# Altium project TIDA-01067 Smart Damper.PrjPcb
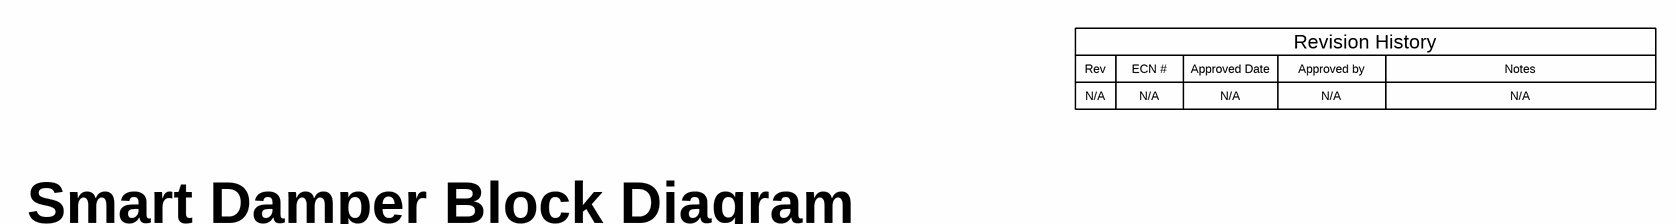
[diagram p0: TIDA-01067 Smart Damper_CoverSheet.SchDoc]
CopyrightYear: 2016; Orderable: N/A; PCB_Layout: Krypton Solutions/RS; PCB_Rev: A; PRJ_Customer: Public Release; PRJ_Engineer: Jarrod Krebs; PRJ_Number: TIDA-01067; PRJ_Title: TIDA-01067 Smart Damper; SCH_Rev: A; TechSupport: http://www.ti.com/support; TID: 01067
4 sheets, 103 parts. Net scope: global (net labels, ports and power ports of the same name join across sheets).
Board file: TIDA-01067 Smart Damper.PcbDoc
Sheets:
  TIDA-01067 Smart Damper_CoverSheet.SchDoc
  TIDA-01067 Smart Damper_Hardware.SchDoc
  TIDA-01067 Smart Damper_Sheet1.SchDoc
  TIDA-01067 Smart Damper_Sheet2.SchDoc

## Sheet TIDA-01067 Smart Damper_CoverSheet.SchDoc: Cover
size 431 x 279 mm; Date: Not shown in title block; ApprovedBy: Not shown in title block; CheckedBy: Not shown in title block; Author: Not shown in title block; CompanyName: Not shown in title block; Engineer: Not shown in title block; Organization: Not shown in title block; Address1: Not shown in title block; Address2: Not shown in title block; Address3: Not shown in title block; Address4: Not shown in title block; DocumentNumber: 1; Revision: Use project parameter SCH_Rev; SheetNumber: 1; SheetTotal: 4; PageSetup: Record=PageOptions¦CenterHorizontal=True¦CenterVertical=True¦PrintScale=1.00¦XCorrection=1.00¦YCorrection=1.00¦PrintKind=0¦BorderSize=5000000¦LeftOffset=0¦BottomOffset=0¦Orientation=2¦PaperLength=1000¦PaperWidth=1000¦Scale=100¦PaperSource=15¦PrintQuality=-3¦MediaType=1¦DitherType=10¦PrintScaleMode=1¦PaperKind=Letter¦PaperIndex=1

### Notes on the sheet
- Rev
- N/A
- ECN #
- Approved Date
- Approved by
- Revision History
- Notes
- Smart Damper Block Diagram

## Sheet TIDA-01067 Smart Damper_Hardware.SchDoc: Hardware
size 431 x 279 mm; Date: Not shown in title block; ApprovedBy: Not shown in title block; CheckedBy: Not shown in title block; Author: Not shown in title block; CompanyName: Not shown in title block; Engineer: Not shown in title block; Organization: Not shown in title block; Address1: Not shown in title block; Address2: Not shown in title block; Address3: Not shown in title block; Address4: Not shown in title block; DocumentNumber: 4; Revision: Use project parameter SCH_Rev; SheetNumber: 4; SheetTotal: 4; PageSetup: Record=PageOptions¦CenterHorizontal=True¦CenterVertical=True¦PrintScale=1.00¦XCorrection=1.00¦YCorrection=1.00¦PrintKind=0¦BorderSize=5000000¦LeftOffset=0¦BottomOffset=0¦Orientation=2¦PaperLength=1000¦PaperWidth=1000¦Scale=100¦PaperSource=15¦PrintQuality=600¦MediaType=1¦DitherType=10¦PaperKind=Letter¦PrintScaleMode=1
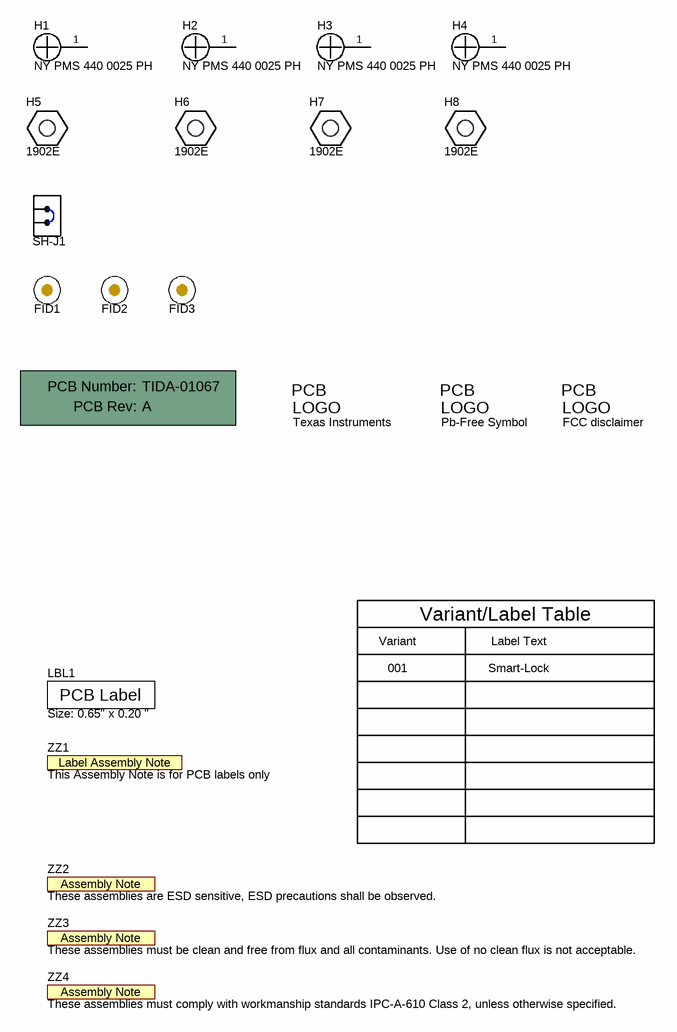
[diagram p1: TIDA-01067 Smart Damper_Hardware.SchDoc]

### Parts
!PCB1  Printed Circuit Board  (value not drawn)  (mechanical)
FID1  Fiducial  [Fiducial10-20]  (value not drawn)
FID2  Fiducial  [Fiducial10-20]  (value not drawn)
FID3  Fiducial  [Fiducial10-20]  (value not drawn)
H1  NY PMS 440 0025 PH  [NY PMS 440 0025 PH]
H2  NY PMS 440 0025 PH  [NY PMS 440 0025 PH]
H3  NY PMS 440 0025 PH  [NY PMS 440 0025 PH]
H4  NY PMS 440 0025 PH  [NY PMS 440 0025 PH]
H5  1902E  [Keystone_1902E]
H6  1902E  [Keystone_1902E]
H7  1902E  [Keystone_1902E]
H8  1902E  [Keystone_1902E]
LBL1  Size: 0.65" x 0.20 "  [Label_650x200]
Logo1  Texas Instruments  [TI_Stacked_Overlay_Small]  (no BOM)
Logo2  Pb-Free Symbol  [Pb-Free_Overlay_Small]  (no BOM)
Logo3  FCC disclaimer  [FCC_disclaimer]  (no BOM)
SH-J1  969102-0000-DA  [SNT-100-BK-G]  (value not drawn)
ZZ1  This Assembly Note is for PCB labels only  [AssemblyNoteLabel]  (no BOM)
ZZ2  These assemblies are ESD sensitive, ESD precautions shall be observed.  [AssemblyNote]  (no BOM)
ZZ3  These assemblies must be clean and free from flux and all contaminants. Use of no clean flux is not acceptable.  [AssemblyNote]  (no BOM)
ZZ4  These assemblies must comply with workmanship standards IPC-A-610 Class 2, unless otherwise specified.  [AssemblyNote]  (no BOM)

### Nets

Not connected (* = marked no-connect by the designer): H1 1; H2 1; H3 1; H4 1

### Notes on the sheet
- Variant
- Variant/Label Table
- Label Text
- 001
- Smart-Lock

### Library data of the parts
!PCB1 = PCB: Manufacturer: Any; PartNumber: TIDA-01067; SymbolCreator: a0412235
FID1-FID3 = Fiducial: Fiducial mark.  There is nothing to buy or mount.; SymbolCreator: codlsc
H1-H4 = NY PMS 440 0025 PH: Machine Screw, Round, #4-40 x 1/4, Nylon, Philips panhead; Manufacturer: B&F Fastener Supply; CompType: Hardware; SymbolCreator: codlsc; U/M: EA
H5-H8 = 1902E: Standoff, Hex, 1"L #4-40 Nylon; Manufacturer: Keystone; CompType: Hardware; SymbolCreator: a0412235
LBL1 = THT-14-423-10: Thermal Transfer Printable Labels, 0.650" W x 0.200" H - 10,000 per roll; Manufacturer: Brady; SymbolCreator: a0412235; CompType: Label
Logo1 = TI_Logo: Texas Instrument Corporate Signature; SymbolCreator: codlsc
Logo2 = Pb-Free: SymbolCreator: a0412235
Logo3 = FCC_disclaimer: SymbolCreator: codlsc
SH-J1 = 969102-0000-DA: Shunt, 100mil, Gold plated, Black; Manufacturer: 3M; Alternate Manufacturer: Samtec; Value: 1x2; Note: You can "mate" this to a header by matching the designator.  i.e. use SH-J3 for header J3
ZZ1 = AssemblyNoteLabel: SymbolCreator: a0412235
ZZ2-ZZ4 = AssemblyNote: SymbolCreator: codlsc

## Sheet TIDA-01067 Smart Damper_Sheet1.SchDoc: Schematic
size 431 x 279 mm; Date: Not shown in title block; ApprovedBy: Not shown in title block; CheckedBy: Not shown in title block; Author: Not shown in title block; CompanyName: Not shown in title block; DrawnBy: Aramis P. Alvarez; Engineer: Not shown in title block; Organization: Not shown in title block; Address1: Not shown in title block; Address2: Not shown in title block; Address3: Not shown in title block; Address4: Not shown in title block; DocumentNumber: 2; Revision: Use project parameter SCH_Rev; SheetNumber: 2; SheetTotal: 4; PageSetup: Record=PageOptions¦CenterHorizontal=True¦CenterVertical=True¦PrintScale=1.00¦XCorrection=1.00¦YCorrection=1.00¦PrintKind=0¦BorderSize=5000000¦LeftOffset=0¦BottomOffset=0¦Orientation=2¦PaperLength=1000¦PaperWidth=1000¦Scale=100¦PaperSource=15¦PrintQuality=600¦MediaType=1¦DitherType=10¦PaperKind=Letter¦PrintScaleMode=1
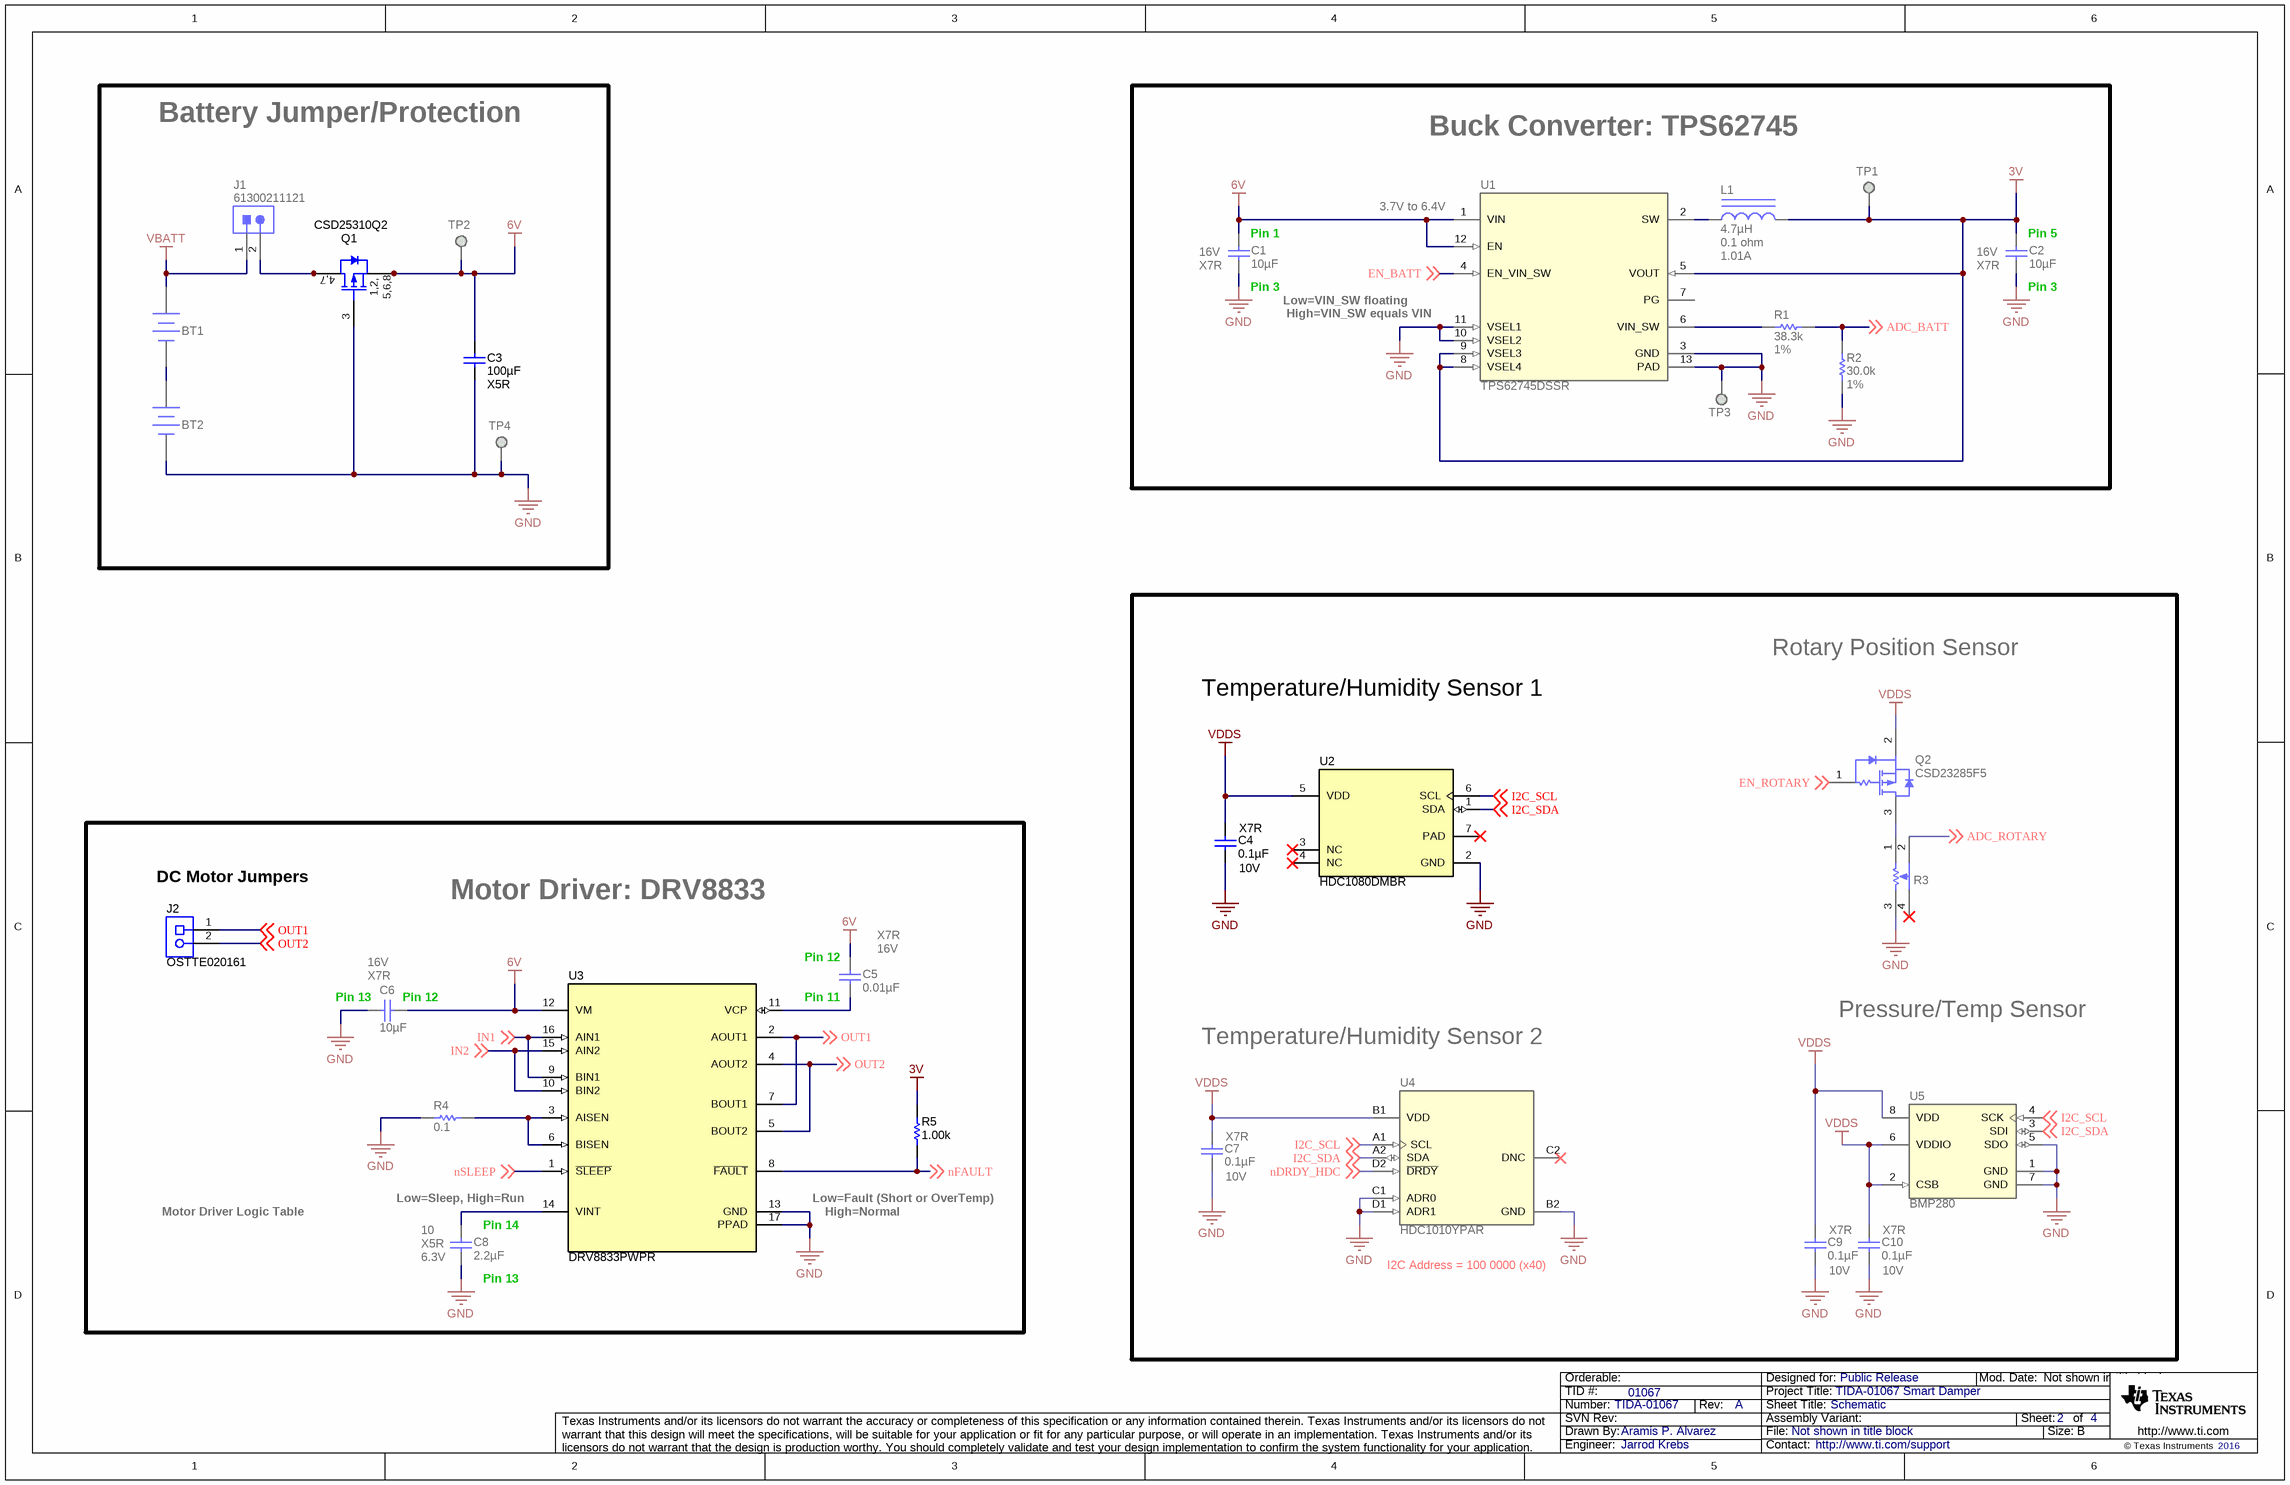
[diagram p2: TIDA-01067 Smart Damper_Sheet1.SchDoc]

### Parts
BT1  2462  [Keystone_2462]  (value not drawn)
BT2  2462  [Keystone_2462]  (value not drawn)
C1  ValueDisplayed: 10µF  Value2: 16V  TempCo: X7R  [0805_HV]  (hidden comment: EMK212BB7106MG-T)
C2  ValueDisplayed: 10µF  Value2: 16V  TempCo: X7R  [0805_HV]  (hidden comment: EMK212BB7106MG-T)
C3  ValueDisplayed: 100µF  TempCo: X5R  [1206_190]  (hidden comment: C3216X5R1A107M160AC)
C4  ValueDisplayed: 0.1µF  Value2: 10V  TempCo: X7R  [0402L]  (hidden comment: GRM155R71A104KA01D)
C5  ValueDisplayed: 0.01µF  Value2: 16V  TempCo: X7R  [0402]  (hidden comment: C1005X7R1C103K050BA)
C6  ValueDisplayed: 10µF  Value2: 16V  TempCo: X7R  [0805_HV]  (hidden comment: EMK212BB7106MG-T)
C7  ValueDisplayed: 0.1µF  Value2: 10V  TempCo: X7R  [0402L]  (hidden comment: GRM155R71A104KA01D)
C8  ValueDisplayed: 2.2µF  Tolerance_%: 10  Value2: 6.3V  TempCo: X5R  [0603]  (hidden comment: C0603C225K9PACTU)
C9  ValueDisplayed: 0.1µF  Value2: 10V  TempCo: X7R  [0402L]  (hidden comment: GRM155R71A104KA01D)
C10  ValueDisplayed: 0.1µF  Value2: 10V  TempCo: X7R  [0402L]  (hidden comment: GRM155R71A104KA01D)
J1  61300211121  [WURTH_61300211121]
J2  OSTTE020161  [On-Shore_OSTTE020161]
L1  ValueDisplayed: 4.7µH  Value1: 0.1 ohm  Value2: 1.01A  [CBC3225]  (hidden comment: CBC3225T4R7MR)
Q1  CSD25310Q2  [TRANS_NexFET_Q2]
Q2  CSD23285F5  [YJK0003A]
R1  ValueDisplayed: 38.3k  Value1: 1%  [0603]  (hidden comment: RC0603FR-0738K3L)
R2  ValueDisplayed: 30.0k  Value1: 1%  [0603]  (hidden comment: ERJ-3EKF3002V)
R3  EVW-AE4001B14  [Panasonic_EVW-AE4001B14]  (value not drawn)
R4  ValueDisplayed: 0.1  [1206]  (hidden comment: CSR1206FKR100)
R5  ValueDisplayed: 1.00k  [0603]  (hidden comment: ERJ-3EKF1001V)
TP1  TESTPOINT  [Keystone_5019]  (value not drawn)  (no BOM)
TP2  TESTPOINT  [Keystone_5019]  (value not drawn)  (no BOM)
TP3  TESTPOINT  [Keystone_5019]  (value not drawn)  (no BOM)
TP4  TESTPOINT  [Keystone_5019]  (value not drawn)  (no BOM)
U1  TPS62745DSSR  [DSS0012A]
U2  HDC1080DMBR  [DMB0006A]
U3  DRV8833PWPR  [PWP0016C_N]
U4  HDC1010YPAR  [YPA0008AGAE]
U5  BMP280  [LGA8-2X2_5MM_0_65]

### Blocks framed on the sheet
Battery Jumper/Protection: BT1 BT2 C3 J1 Q1 TP2 TP4
Buck Converter: TPS62745: C1 C2 L1 R1 R2 TP1 TP3 U1
I2C Address = 100 0000 (x40): C4 C7 C9 C10 Q2 R3 U2 U4 U5
Motor Driver: DRV8833: C5 C6 C8 J2 R4 R5 U3

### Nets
3V: C2.2 L1.2 R5.2 TP1.1 U1.5(VOUT) U1.8(VSEL4) U1.9(VSEL3)
6V: C1.2 C3.2 C5.2 C6.2 Q1.1(S) Q1.2(S) Q1.5(S) Q1.6(S) Q1.8(S) TP2.1 U1.1(VIN) U1.12(EN) U3.12(VM)
GND: BT2.2(-) C1.1 C2.1 C3.1 C4.1 C6.1 C7.1 C8.2 C9.1 C10.1 Q1.3(G) R2.2 R3.3 R4.1 TP3.1 TP4.1 U1.3(GND) U1.10(VSEL2) U1.11(VSEL1) U1.13(PAD) U2.2(GND) U3.13(GND) U3.17(PPAD) U4.B2(GND) U4.C1(ADR0) U4.D1(ADR1) U5.1(GND) U5.5(SDO) U5.7(GND)
VBATT: BT1.1(+) J1.1
VDDS: C4.2 C7.2 C9.2 C10.2 Q2.2(S) U2.5(VDD) U4.B1(VDD) U5.2(CSB) U5.6(VDDIO) U5.8(VDD)
ADC_BATT: R1.1 R2.1 ; off-sheet ADC_BATT
ADC_ROTARY: R3.2 ; off-sheet ADC_ROTARY
EN_BATT: U1.4(EN_VIN_SW) ; off-sheet EN_BATT
EN_ROTARY: Q2.1(G) ; off-sheet EN_ROTARY
I2C_SCL: U2.6(SCL) U4.A1(SCL) U5.4(SCK) ; off-sheet I2C_SCL
I2C_SDA: U2.1(SDA) U4.A2(SDA) U5.3(SDI) ; off-sheet I2C_SDA
IN1: U3.9(BIN1) U3.16(AIN1) ; off-sheet IN1
IN2: U3.10(BIN2) U3.15(AIN2) ; off-sheet IN2
nDRDY_HDC: U4.D2(~{DRDY}) ; off-sheet nDRDY_HDC
nFAULT: R5.1 U3.8(~{FAULT}) ; off-sheet nFAULT
nSLEEP: U3.1(~{SLEEP}) ; off-sheet nSLEEP
OUT1: J2.1 U3.2(AOUT1) U3.7(BOUT1) ; off-sheet OUT1
OUT2: J2.2 U3.4(AOUT2) U3.5(BOUT2) ; off-sheet OUT2
NetBT1_2: BT1.2(-) BT2.1(+)
NetC5_1: C5.1 U3.11(VCP)
NetC8_1: C8.1 U3.14(VINT)
NetJ1_2: J1.2 Q1.4(D) Q1.7(D)
NetL1_1: L1.1 U1.2(SW)
NetQ2_3: Q2.3(D) R3.1
NetR1_2: R1.2 U1.6(VIN_SW)
NetR4_2: R4.2 U3.3(AISEN) U3.6(BISEN)

Not connected (* = marked no-connect by the designer): R3 4*; U1 7(PG); U2 3(NC)* 4(NC)* 7(PAD)*; U4 C2(DNC)*

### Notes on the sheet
- (near C1) Pin 1
- (near U1) 3.7V to 6.4V
- (near C2) Pin 5
- (near C1) Pin 3
- Low=VIN_SW floating
- (near C2) Pin 3
- High=VIN_SW equals VIN
- Temperature/Humidity Sensor 1
- Rotary Position Sensor
- (near J2) DC Motor Jumpers
- (near C5) Pin 12
- (near C6) Pin 13
- (near C6) Pin 12
- (near C5) Pin 11
- Pressure/Temp Sensor
- Temperature/Humidity Sensor 2
- Motor Driver Logic Table
- Low=Sleep, High=Run
- (near C8) Pin 14
- High=Normal
- Low=Fault (Short or OverTemp)
- (near C8) Pin 13

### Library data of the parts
BT1 BT2 = 2462: 2x AA Battery Holder, Through-hole mount; Manufacturer: Keystone
C1 C2 C6 = EMK212BB7106MG-T: CAP, CERM, 10 µF, 16 V, +/- 20%, X7R, 0805; Manufacturer: Taiyo Yuden; Polarized: N; CompType: Capacitor; Value: 10uF; U/M: EA; Cap_F: 0.00001; Tolerance_%: 20; Value1: Unknown; VDC_V: 16; TaMin_C: -55; TaMax_C: 125; Cap_Case: 0805; AEC Category: Q200
C3 = C3216X5R1A107M160AC: CAP, CERM, 100 µF, 10 V, +/- 20%, X5R, 1206_190; Manufacturer: TDK; Polarized: N; CompType: Capacitor; Value: 100uF; U/M: EA; Cap_F: 0.0001; Tolerance_%: 20; Value1: Unknown; VDC_V: 10; Value2: 10V; TaMin_C: -55; TaMax_C: 85; Cap_Case: 1206; AEC Category: Q200
C4 C7 C9 C10 = GRM155R71A104KA01D: CAP, CERM, 0.1 µF, 10 V, +/- 10%, X7R, 0402; Manufacturer: MuRata; Polarized: N; CompType: Capacitor; Value: 0.1uF; U/M: EA; Cap_F: 0.0000001; Tolerance_%: 10; Value1: Unknown; TaMin_C: -55; TaMax_C: 125; Cap_Case: 0402; AEC Category: Q200
C5 = C1005X7R1C103K050BA: CAP, CERM, 0.01 µF, 16 V, +/- 10%, X7R, 0402; Manufacturer: TDK; Polarized: N; CompType: Capacitor; Value: 0.01uF; U/M: EA; Cap_F: 0.00000001; Tolerance_%: 10; ESR_ohm: 0.0623; Value1: 0.0623 ohm; VDC_V: 16; TaMin_C: -55; TaMax_C: 125; AEC Category: Q200
C8 = C0603C225K9PACTU: CAP, CERM, 2.2 µF, 6.3 V, +/- 10%, X5R, 0603; Manufacturer: Kemet; Polarized: N; CompType: Capacitor; Value: 2.2uF; U/M: EA; Cap_F: 0.0000022; Value1: Unknown; VDC_V: 6.3; TaMin_C: -55; TaMax_C: 85; AEC Category: Q200
J1 = 61300211121: Header, 2.54 mm, 2x1, Gold, TH; Manufacturer: Wurth Elektronik eiSos; SymbolCreator: a0412235; U/M: EA
J2 = OSTTE020161: Terminal Block, 2x1, 3.5mm, TH; Manufacturer: On-Shore Technology; SymbolCreator: a0412235
L1 = CBC3225T4R7MR: Inductor, Wirewound, 4.7 µH, 1.01 A, 0.1 ohm, SMD; Manufacturer: Taiyo Yuden; Value: 4.7uH; Ind_H: 4.7E-6; Imax_A: 1.01; Irms: 1.04A @ 40C rise; Isat: 1.25A @ 30% inductance drop; DCR_ohm: 0.1; AEC Category: Q200; AEC Qualified: N
Q1 = CSD25310Q2: MOSFET, P-CH, -20 V, -20 A, SON 2x2mm; Manufacturer: Texas Instruments; Alternate Manufacturer: None; SymbolCreator: a0411947; U/M: EA; ChType: P; Value: -20V; Value1: 0.0239 ohm; Rdson45_ohm: 0.0239; Value2: 3.6 nC; QgTyp_nC: 3.6; Vgs_V: -8; AEC Category: Q101
Q2 = CSD23285F5: MOSFET, P-CH, -12 V, -3.3 A, YJK0003A (PICOSTAR-3); Manufacturer: Texas Instruments; Alternate Manufacturer: None; SymbolCreator: a0411947; U/M: EA; ChType: P; Value: -12V; Value1: 0.035 ohm; Rdson45_ohm: 0.035; Value2: 3.2 nC; QgTyp_nC: 3.2; Vgs_V: -6; SizeAreaWB_mm2: 4.3077; SizeArea_mm2: 1.0877; SizeX_mm: 1.49; SizeY_mm: 0.73; SizeZ_mm: 0.35; AEC Category: Q101; AEC Qualified: N
R1 = RC0603FR-0738K3L: RES, 38.3 k, 1%, 0.1 W, 0603; Manufacturer: Yageo America; CompType: Resistor; Value: 38.3k; Res_ohm: 38300; Value_Code: 38k3; Tolerance_%: 1; Power_W: 0.1; Value2: 0.1W; VDC_V: 150; TempCo: 200 ppm/C; EIA_Code: E96; U/M: EA; AEC Category: Q200
R2 = ERJ-3EKF3002V: RES, 30.0 k, 1%, 0.1 W, AEC-Q200 Grade 0, 0603; Manufacturer: Panasonic; CompType: Resistor; Value: 30.0k; Res_ohm: 30000; Value_Code: 30k0; Tolerance_%: 1; Power_W: 0.1; Value2: 0.1W; VDC_V: 75; TempCo: 100 ppm/C; U/M: EA; AEC Category: Q200; AEC Qualified: Y; AEC Grade: 0
R3 = EVW-AE4001B14: 10 mm GS Sensor, SMD; Manufacturer: Panasonic; SymbolCreator: Altium; SizeAreaWB_mm2: 219.24; SizeArea_mm2: 163.24; SizeX_mm: 15.4; SizeY_mm: 10.6; SizeZ_mm: 2.2
R4 = CSR1206FKR100: RES, 0.1, 1%, 0.5 W, 1206; Manufacturer: Stackpole Electronics Inc; CompType: Resistor; Value: 0.1; Value_Code: R100; Tolerance_%: 1; Power_W: 0.5; Value2: 0.5W; TempCo: 100 ppm/C; EIA_Code: E96; U/M: EA; AEC Category: Q200
R5 = ERJ-3EKF1001V: RES, 1.00 k, 1%, 0.1 W, 0603; Manufacturer: Panasonic; CompType: Resistor; Value: 1.00k; Res_ohm: 1000; Value_Code: 1k00; Tolerance_%: 1; Power_W: 0.1; Value2: 0.1W; VDC_V: 75; TempCo: 100 ppm/C; EIA_Code: E96; U/M: EA; AEC Category: Q200
TP1-TP4 = 5019: Test Point, Miniature, SMT; Manufacturer: Keystone; CompType: Test Point Loop
U1 = TPS62745DSSR: Dual-cell Ultra Low IQ Step Down Converter for Low Power Wireless Applications, DSS0012A; Alternate PartNumber: TPS62745DSST; Manufacturer: Texas Instruments; SymbolCreator: a0411947; CompType: IC; U/M: EA
U2 = HDC1080DMBR: HDC1080 Low Power, High Accuracy Digital Humidity Sensor with Temperature Sensor, DMB0006A (WSON-6); Alternate PartNumber: HDC1080DMBT; Manufacturer: Texas Instruments; SymbolCreator: a0411947; SizeArea_mm2: 9; SizeAreaWB_mm2: 16; SizeX_mm: 3; SizeZ_mm: 0.8; CompType: IC; U/M: EA
U3 = DRV8833PWPR: Dual H-Bridge Motor Driver, PWP0016C; Manufacturer: Texas Instruments; SymbolCreator: a0411947; CompType: IC; U/M: EA
U4 = HDC1010YPAR: Low Power, High Accuracy Digital Humidity Sensor with Temperature Sensor, YPA0008AGAE (DSBGA-8); Alternate PartNumber: HDC1010YPAT; Manufacturer: Texas Instruments; SymbolCreator: Altium; SizeArea_mm2: 3.2436; SizeAreaWB_mm2: 7.8736; SizeX_mm: 1.59; SizeY_mm: 2.04; SizeZ_mm: 0.675; CompType: IC; U/M: EA
U5 = BMP280: Digital Pressure Sensor, LGA8-2X2_5MM_0_65; Manufacturer: Bosch Solar Energy; SymbolCreator: Altium

## Sheet TIDA-01067 Smart Damper_Sheet2.SchDoc: Schematic
size 431 x 279 mm; Date: Not shown in title block; ApprovedBy: Not shown in title block; CheckedBy: Not shown in title block; Author: Not shown in title block; CompanyName: Not shown in title block; Engineer: Not shown in title block; Organization: Not shown in title block; Address1: Not shown in title block; Address2: Not shown in title block; Address3: Not shown in title block; Address4: Not shown in title block; DocumentNumber: 3; Revision: Use project parameter SCH_Rev; SheetNumber: 3; SheetTotal: 4; PageSetup: Record=PageOptions¦CenterHorizontal=True¦CenterVertical=True¦PrintScale=1.00¦XCorrection=1.00¦YCorrection=1.00¦PrintKind=0¦BorderSize=5000000¦LeftOffset=0¦BottomOffset=0¦Orientation=2¦PaperLength=1000¦PaperWidth=1000¦Scale=100¦PaperSource=15¦PrintQuality=600¦MediaType=1¦DitherType=10¦PaperKind=Letter¦PrintScaleMode=1
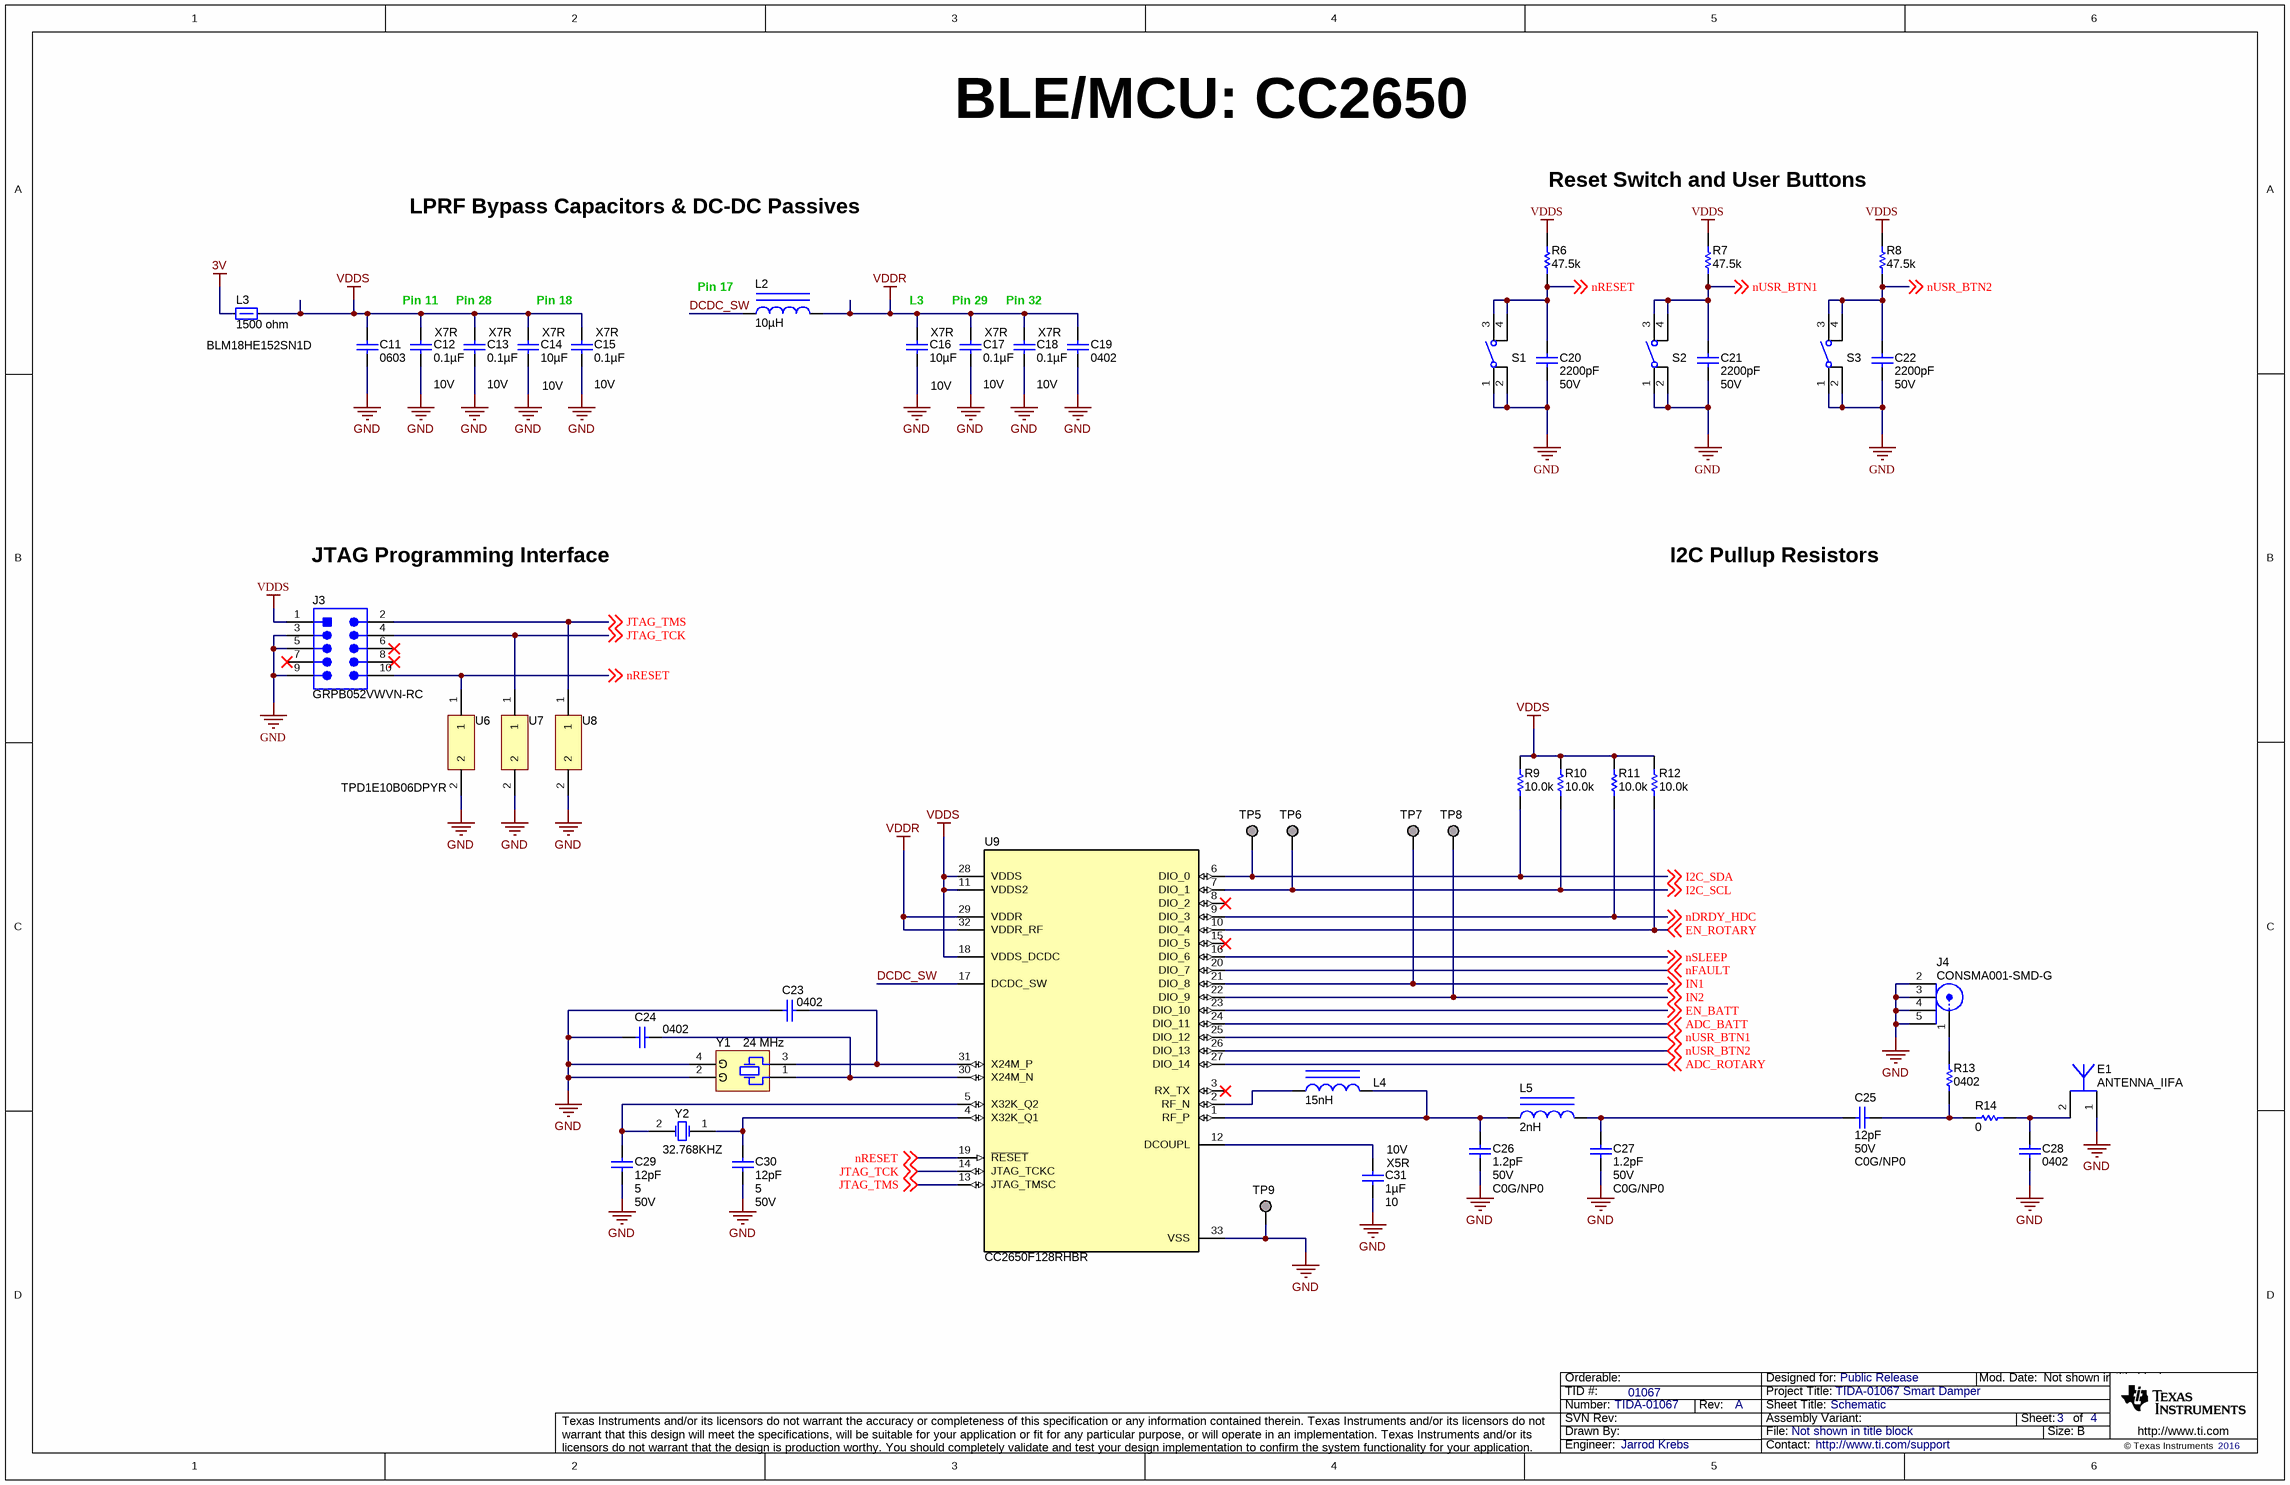
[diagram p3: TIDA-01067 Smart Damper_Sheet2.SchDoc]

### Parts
C11  C1608X5R1A106M080AC  [0603]  (value not drawn)
C12  ValueDisplayed: 0.1µF  Value2: 10V  TempCo: X7R  [0402]  (hidden comment: GRM155R71A104KA01D)
C13  ValueDisplayed: 0.1µF  Value2: 10V  TempCo: X7R  [0402]  (hidden comment: GRM155R71A104KA01D)
C14  ValueDisplayed: 10µF  Value2: 10V  TempCo: X7R  [0805_HV]  (hidden comment: GRM21BR71A106KE51L)
C15  ValueDisplayed: 0.1µF  Value2: 10V  TempCo: X7R  [0402S]  (hidden comment: GRM155R71A104KA01D)
C16  ValueDisplayed: 10µF  Value2: 10V  TempCo: X7R  [0805_HV]  (hidden comment: GRM21BR71A106KE51L)
C17  ValueDisplayed: 0.1µF  Value2: 10V  TempCo: X7R  [0402L]  (hidden comment: GRM155R71A104KA01D)
C18  ValueDisplayed: 0.1µF  Value2: 10V  TempCo: X7R  [0402L]  (hidden comment: GRM155R71A104KA01D)
C19  Cap_Case: 0402  [0402L]  (hidden comment: 885012205037)
C20  ValueDisplayed: 2200pF  Value2: 50V  [0402]  (hidden comment: C1005X7R1H222K)
C21  ValueDisplayed: 2200pF  Value2: 50V  [0402]  (hidden comment: C1005X7R1H222K)
C22  ValueDisplayed: 2200pF  Value2: 50V  [0402]  (hidden comment: C1005X7R1H222K)
C23  GRM1555C1H120JA01D  [0402]  (value not drawn)
C24  GRM1555C1H120JA01D  [0402]  (value not drawn)
C25  ValueDisplayed: 12pF  Value2: 50V  TempCo: C0G/NP0  [0402L]  (hidden comment: GRM1555C1H120JA01D)
C26  ValueDisplayed: 1.2pF  Value2: 50V  TempCo: C0G/NP0  [0402L]  (hidden comment: GRM1555C1H1R2CA01D)
C27  ValueDisplayed: 1.2pF  Value2: 50V  TempCo: C0G/NP0  [0402L]  (hidden comment: GRM1555C1H1R2CA01D)
C28  GRM1555C1H1R2CA01D  [0402]  (value not drawn)
C29  ValueDisplayed: 12pF  Tolerance_%: 5  Value2: 50V  [0402]  (hidden comment: GRM1555C1H120JA01D)
C30  ValueDisplayed: 12pF  Tolerance_%: 5  Value2: 50V  [0402]  (hidden comment: GRM1555C1H120JA01D)
C31  ValueDisplayed: 1µF  Tolerance_%: 10  Value2: 10V  TempCo: X5R  [0402]  (hidden comment: GRM155R61A105KE15D)
E1  ANTENNA_IIFA  [ANTENNA_IIFA]  (net tie)
J3  GRPB052VWVN-RC  [CONN_GRPB052VWVN-RC]
J4  CONSMA001-SMD-G  [Linx_CONSMA001-SMD-G]
L2  ValueDisplayed: 10µH  [0805_145]  (hidden comment: CKS2125100M-T)
L3  value 1500 ohm  [0603]  (hidden comment: BLM18HE152SN1D)
L4  ValueDisplayed: 15nH  [IND_LQG15H]  (hidden comment: LQG15HS15NJ02D)
L5  ValueDisplayed: 2nH  [IND_LQG15H]  (hidden comment: LQG15HS2N0S02D)
R6  ValueDisplayed: 47.5k  [0402]  (hidden comment: CRCW040247K5FKED)
R7  ValueDisplayed: 47.5k  [0402]  (hidden comment: CRCW040247K5FKED)
R8  ValueDisplayed: 47.5k  [0402]  (hidden comment: CRCW040247K5FKED)
R9  ValueDisplayed: 10.0k  [0402]  (hidden comment: CRCW040210K0FKED)
R10  ValueDisplayed: 10.0k  [0402]  (hidden comment: CRCW040210K0FKED)
R11  ValueDisplayed: 10.0k  [0402]  (hidden comment: CRCW040210K0FKED)
R12  ValueDisplayed: 10.0k  [0402]  (hidden comment: CRCW040210K0FKED)
R13  PackageReference: 0402  [0402L]  (hidden comment: CRCW04021K00JNED)
R14  ValueDisplayed: 0  [0402L]  (hidden comment: ERJ-2GE0R00X)
S1  4-1437565-1  [SW_FSM4JSMA]  (value not drawn)
S2  4-1437565-1  [SW_FSM4JSMA]  (value not drawn)
S3  4-1437565-1  [SW_FSM4JSMA]  (value not drawn)
TP5  TESTPOINT  [Keystone_5019]  (value not drawn)  (no BOM)
TP6  TESTPOINT  [Keystone_5019]  (value not drawn)  (no BOM)
TP7  TESTPOINT  [Keystone_5019]  (value not drawn)  (no BOM)
TP8  TESTPOINT  [Keystone_5019]  (value not drawn)  (no BOM)
TP9  TESTPOINT  [Keystone_5019]  (value not drawn)  (no BOM)
U6  TPD1E10B06DPYR  [DPY0002A]  (value not drawn)
U7  TPD1E10B06DPYR  [DPY0002A]  (value not drawn)
U8  TPD1E10B06DPYR  [DPY0002A]
U9  CC2650F128RHBR  [RHB0032E]
Y1  Frequency: 24 MHz  [EPSON_TSX-3225]  (hidden comment: TSX-3225 24.0000MF20G-AC3)
Y2  Frequency: 32.768KHZ  [Epson_FC-12M]  (hidden comment: FC-12M 32.7680KA-A3)

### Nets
3V: L3.1
GND: C11.2 C12.1 C13.1 C14.2 C15.1 C16.2 C17.1 C18.1 C19.2 C20.1 C21.1 C22.1 C23.1 C24.1 C26.2 C27.2 C28.1 C29.1 C30.2 C31.1 E1.1 J3.3 J3.5 J3.9 J4.2 J4.3 J4.4 J4.5 S1.1 S1.2 S2.1 S2.2 S3.1 S3.2 TP9.1 U6.2 U7.2 U8.2 U9.33(VSS) Y1.2(GND) Y1.4(GND)
VDDR: C16.1 C17.2 C18.2 C19.1 L2.2 U9.29(VDDR) U9.32(VDDR_RF)
VDDS: C11.1 C12.2 C13.2 C14.1 C15.2 J3.1 L3.2 R6.2 R7.2 R8.2 R9.2 R10.2 R11.2 R12.2 U9.11(VDDS2) U9.18(VDDS_DCDC) U9.28(VDDS)
ADC_BATT: U9.24(DIO_11) ; off-sheet ADC_BATT
ADC_ROTARY: U9.27(DIO_14) ; off-sheet ADC_ROTARY
DCDC_SW: L2.1 U9.17(DCDC_SW)
EN_BATT: U9.23(DIO_10) ; off-sheet EN_BATT
EN_ROTARY: R12.1 U9.10(DIO_4) ; off-sheet EN_ROTARY
I2C_SCL: R10.1 TP6.1 U9.7(DIO_1) ; off-sheet I2C_SCL
I2C_SDA: R9.1 TP5.1 U9.6(DIO_0) ; off-sheet I2C_SDA
IN1: TP7.1 U9.21(DIO_8) ; off-sheet IN1
IN2: TP8.1 U9.22(DIO_9) ; off-sheet IN2
JTAG_TCK: J3.4 U7.1 U9.14(JTAG_TCKC) ; off-sheet JTAG_TCK
JTAG_TMS: J3.2 U8.1 U9.13(JTAG_TMSC) ; off-sheet JTAG_TMS
nDRDY_HDC: R11.1 U9.9(DIO_3) ; off-sheet nDRDY_HDC
nFAULT: U9.20(DIO_7) ; off-sheet nFAULT
nRESET: C20.2 J3.10 R6.1 S1.3 S1.4 U6.1 U9.19(~{RESET}) ; off-sheet nRESET
nSLEEP: U9.16(DIO_6) ; off-sheet nSLEEP
nUSR_BTN1: C21.2 R7.1 S2.3 S2.4 U9.25(DIO_12) ; off-sheet nUSR_BTN1
nUSR_BTN2: C22.2 R8.1 S3.3 S3.4 U9.26(DIO_13) ; off-sheet nUSR_BTN2
NetC23_2: C23.2 U9.31(X24M_P) Y1.3
NetC24_2: C24.2 U9.30(X24M_N) Y1.1
NetC25_1: C25.1 R13.1 R14.1
NetC25_2: C25.2 C27.1 L5.2
NetC26_1: C26.1 L4.2 L5.1 U9.1(RF_P)
NetC28_2: C28.2 E1.2 R14.2
NetC29_2: C29.2 U9.5(X32K_Q2) Y2.2(OSC2)
NetC30_1: C30.1 U9.4(X32K_Q1) Y2.1(OSC1)
NetC31_2: C31.2 U9.12(DCOUPL)
NetJ4_1: J4.1 R13.2
NetL4_1: L4.1 U9.2(RF_N)

Not connected (* = marked no-connect by the designer): J3 6* 7* 8*; U9 3(RX_TX)* 8(DIO_2)* 15(DIO_5)*

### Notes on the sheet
- BLE/MCU: CC2650
- LPRF Bypass Capacitors & DC-DC Passives
- Reset Switch and User Buttons
- Pin 11
- Pin 28
- Pin 18
- (near L2) Pin 17
- (near C16) L3
- Pin 29
- Pin 32
- JTAG Programming Interface
- I2C Pullup Resistors

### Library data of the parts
C11 = C1608X5R1A106M080AC: CAP, CERM, 10 µF, 10 V, +/- 20%, X5R, 0603; Manufacturer: TDK; Polarized: N; CompType: Capacitor; Value: 10uF; ValueDisplayed: 10µF; U/M: EA; Cap_F: 0.00001; Tolerance_%: 20; ESR_ohm: 0.0078; Value1: 0.0078 ohm; VDC_V: 10; Value2: 10V; IRMS_A: 1.85; TaMin_C: -55; TaMax_C: 85; AEC Category: Q200
C12 C13 = GRM155R71A104KA01D: CAP, CERM, 0.1 µF, 10 V, +/- 10%, X7R, 0402; Manufacturer: MuRata; Polarized: N; CompType: Capacitor; Value: 0.1uF; U/M: EA; Cap_F: 0.0000001; Tolerance_%: 10; Value1: Unknown; TaMin_C: -55; TaMax_C: 125; AEC Category: Q200
C14 C16 = GRM21BR71A106KE51L: CAP, CERM, 10 µF, 10 V, +/- 10%, X7R, 0805; Manufacturer: MuRata; Polarized: N; CompType: Capacitor; Value: 10uF; U/M: EA; Cap_F: 0.00001; Tolerance_%: 10; ESR_ohm: 0.003; Value1: 0.003 ohm; TaMin_C: -55; TaMax_C: 125; Cap_Case: 0805; AEC Category: Q200
C15 C17 C18 = GRM155R71A104KA01D: as C4 on sheet TIDA-01067 Smart Damper_Sheet1
C19 = 885012205037: CAP, CERM, 0.1 µF, 16 V, +/- 10%, X7R, 0402; Manufacturer: Wurth Elektronik; Polarized: N; CompType: Capacitor; Value: 0.1uF; ValueDisplayed: 0.1µF; U/M: EA; Cap_F: 0.0000001; Tolerance_%: 10; Value1: Unknown; VDC_V: 16; Value2: 16V; TaMin_C: -55; TaMax_C: 125; AEC Category: Q200
C20-C22 = C1005X7R1H222K: CAP, CERM, 2200 pF, 50 V, +/- 10%, X7R, 0402; Manufacturer: TDK; Polarized: N; CompType: Capacitor; Value: 2200pF; U/M: EA; Cap_F: 0.0000000022; Tolerance_%: 10; ESR_ohm: 0.1433; Value1: 0.1433 ohm; VDC_V: 50; TaMin_C: -55; TaMax_C: 125
C23 C24 = GRM1555C1H120JA01D: CAP, CERM, 12 pF, 50 V, +/- 5%, C0G/NP0, 0402; Manufacturer: MuRata; Polarized: N; CompType: Capacitor; Value: 12pF; U/M: EA; Cap_F: 0.000000000012; Tolerance_%: 5; Value1: Unknown; VDC_V: 50; Value2: 50V; TaMin_C: -55; TaMax_C: 125; AEC Category: Q200
C25 = GRM1555C1H120JA01D: CAP, CERM, 12 pF, 50 V, +/- 5%, C0G/NP0, 0402; Manufacturer: MuRata; Polarized: N; CompType: Capacitor; Value: 12pF; U/M: EA; Cap_F: 0.000000000012; Tolerance_%: 5; Value1: Unknown; VDC_V: 50; TaMin_C: -55; TaMax_C: 125; Cap_Case: 0402; AEC Category: Q200
C26 C27 = GRM1555C1H1R2CA01D: CAP, CERM, 1.2 pF, 50 V, +/- 5%, C0G/NP0, 0402; Manufacturer: MuRata; Polarized: N; CompType: Capacitor; Value: 1.2pF; U/M: EA; Cap_F: 0.0000000000012; Tolerance_%: 5; Value1: Unknown; VDC_V: 50; TaMin_C: -55; TaMax_C: 125; Cap_Case: 0402; AEC Category: Q200
C28 = GRM1555C1H1R2CA01D: CAP, CERM, 1.2 pF, 50 V, +/- 5%, C0G/NP0, 0402; Manufacturer: MuRata; Polarized: N; CompType: Capacitor; Value: 1.2pF; U/M: EA; Cap_F: 0.0000000000012; Tolerance_%: 5; Value1: Unknown; VDC_V: 50; Value2: 50V; TaMin_C: -55; TaMax_C: 125; AEC Category: Q200
C29 C30 = GRM1555C1H120JA01D: CAP, CERM, 12 pF, 50 V, +/- 5%, C0G/NP0, 0402; Manufacturer: MuRata; Polarized: N; CompType: Capacitor; Value: 12pF; U/M: EA; Cap_F: 0.000000000012; Value1: Unknown; VDC_V: 50; TaMin_C: -55; TaMax_C: 125; AEC Category: Q200
C31 = GRM155R61A105KE15D: CAP, CERM, 1 µF, 10 V, +/- 10%, X5R, 0402; Manufacturer: MuRata; Polarized: N; CompType: Capacitor; Value: 1uF; U/M: EA; Cap_F: 0.000001; Value1: Unknown; TaMin_C: -55; TaMax_C: 85; AEC Category: Q200
E1 = ANTENNA_IIFA: PCB Antenna.  There is nothing to buy or mount.; SymbolCreator: Altium
J3 = GRPB052VWVN-RC: Header, 50mil, 5x2, Gold, TH; Manufacturer: Sullins Connector Solutions; SymbolCreator: a0412235; U/M: EA
J4 = CONSMA001-SMD-G: Jack, SMA, PCB, Gold, SMT; Manufacturer: Linx Technologies; SymbolCreator: X0208326; U/M: EA
L2 = CKS2125100M-T: Inductor, Multilayer, Ferrite, 10 µH, 0.11 A, 0.52 ohm, SMD; Manufacturer: Taiyo Yuden; Value: 10uH; Ind_H: 10.0E-6; Imax_A: 0.11; DCR_ohm: 0.52; Value2: 0.11A; AEC Category: Q200
L3 = BLM18HE152SN1D: Ferrite Bead, 1500 ohm @ 100 MHz, 0.5 A, 0603; Manufacturer: MuRata; Imax_A: 0.5; Value1: 0.5 ohm; Value2: 0.5A; ZTyp@100MHz_Ohm: 1500
L4 = LQG15HS15NJ02D: Inductor, Multilayer, Air Core, 15 nH, 0.3 A, 0.32 ohm, SMD; Manufacturer: MuRata; Value: 15nH; Ind_H: 15.0E-9; Imax_A: 0.3; Irms: 0.3A @ C rise; Isat: 0.3A @ % inductance drop; DCR_ohm: 0.32; Value2: 0.3A; AEC Category: Q200
L5 = LQG15HS2N0S02D: Inductor, Multilayer, Air Core, 2 nH, 0.3 A, 0.1 ohm, SMD; Manufacturer: MuRata; Value: 2nH; Ind_H: 2.0E-9; Imax_A: 0.3; Irms: 0.3A @ C rise; Isat: 0.3A @ % inductance drop; DCR_ohm: 0.1; Value1: 0.1 ohm; Value2: 0.3A; AEC Category: Q200
R6-R8 = CRCW040247K5FKED: RES, 47.5 k, 1%, 0.063 W, 0402; Manufacturer: Vishay-Dale; CompType: Resistor; Res_ohm: 47500; Value: 47.5k; Value_Code: 47k5; Tolerance_%: 1; Power_W: 0.063; Value2: 0.063W; VDC_V: 50; TempCo: 100 ppm/C; EIA_Code: E96; U/M: EA
R9 R10 = CRCW040210K0FKED: RES, 10.0 k, 1%, 0.063 W, 0402; Manufacturer: Vishay-Dale; CompType: Resistor; Value: 10.0k; Res_ohm: 10000; Value_Code: 10k0; Tolerance_%: 1; Power_W: 0.063; Value2: 0.063W; VDC_V: 50; TempCo: 100 ppm/C; EIA_Code: E96; U/M: EA; AEC Category: Q200; SizeArea_mm2: 0.5; SizeZ_mm: 0.6
R11 R12 = CRCW040210K0FKED: RES, 10.0 k, 1%, 0.063 W, 0402; Manufacturer: Vishay-Dale; CompType: Resistor; Value: 10.0k; Res_ohm: 10000; Value_Code: 10k0; Tolerance_%: 1; Power_W: 0.063; Value2: 0.063W; VDC_V: 50; TempCo: 100 ppm/C; EIA_Code: E96; U/M: EA
R13 = CRCW04021K00JNED: RES, 1.0 k, 5%, 0.063 W, 0402; Manufacturer: Vishay-Dale; CompType: Resistor; Value: 1.0k; Res_ohm: 1000; Value_Code: 1k00; Tolerance_%: 5; Power_W: 0.063; Value2: 0.063W; VDC_V: 50; TempCo: 200 ppm/C; EIA_Code: E24; U/M: EA; AEC Category: Q200
R14 = ERJ-2GE0R00X: RES, 0, 5%, 0.063 W, 0402; Manufacturer: Panasonic; CompType: Resistor; Value: 0; Value_Code: 0000; Tolerance_%: 5; Power_W: 0.063; Value2: 0.063W; VDC_V: 50; TempCo: 600 ppm/C; EIA_Code: E24; U/M: EA; AEC Category: Q200
S1-S3 = 4-1437565-1: Switch, Tactile, SPST-NO, 0.05A, 12V, SMT; Manufacturer: TE Connectivity; SymbolCreator: a0412235; VDC_V: 12; SwitchFunction: Off-Mom; PositionCount: 1; CurrentRating_mA: 50
TP5-TP9 = 5019: as TP1 on sheet TIDA-01067 Smart Damper_Sheet1
U6-U8 = TPD1E10B06DPYR: ESD in 0402 Package with 10 pF Capacitance and 6 V Breakdown, 1 Channel, -40 to +125 degC, 2-pin X2SON (DPY), Green (RoHS & no Sb/Br); Manufacturer: Texas Instruments; Alternate Manufacturer: None; Alternate PartNumber: Equivalent; Breakdown Voltage(Min)(V): 6; Eco-Plan: TBD; IEC 61000-4-2 Air-Gap(+/- kV): 30; IO Capacitance(Typ)(pF): 10; SubFamily: ESD Solution
U9 = CC2650F128RHBR: Ultra low-power ARM Cortex M3 2.4 GHz Radio MCU, Multi-Protocol, RSHB032E (VQFN-32); Alternate PartNumber: CC2650F128RHBT; Manufacturer: Texas Instruments; SymbolCreator: a0412235; CompType: IC; U/M: EA; SizeArea_mm2: 25; SizeAreaWB_mm2: 49; SizeX_mm: 5; SizeZ_mm: 1
Y1 = TSX-3225 24.0000MF20G-AC3: Crystal, 24 MHz, 9 pF, SMD; Manufacturer: Epson; SymbolCreator: a0412235; U/M: EA; TaMin_C: -40; TaMax_C: 85; Frequency Stability: ±20ppm
Y2 = FC-12M 32.7680KA-A3: Crystal, 32.768kHz, 12.5pF, SMD; Manufacturer: Epson; SymbolCreator: a0412235; U/M: EA; TaMin_C: -40; TaMax_C: 85; Frequency Stability: ±20ppm

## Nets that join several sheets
3V: TIDA-01067 Smart Damper_Sheet1 (7 pins), TIDA-01067 Smart Damper_Sheet2 (L3.1)
GND: TIDA-01067 Smart Damper_Sheet1 (29 pins), TIDA-01067 Smart Damper_Sheet2 (41 pins)
VDDS: TIDA-01067 Smart Damper_Sheet1 (10 pins), TIDA-01067 Smart Damper_Sheet2 (17 pins)
ADC_BATT: TIDA-01067 Smart Damper_Sheet1 (R1.1 R2.1), TIDA-01067 Smart Damper_Sheet2 (U9.24)
ADC_ROTARY: TIDA-01067 Smart Damper_Sheet1 (R3.2), TIDA-01067 Smart Damper_Sheet2 (U9.27)
EN_BATT: TIDA-01067 Smart Damper_Sheet1 (U1.4), TIDA-01067 Smart Damper_Sheet2 (U9.23)
EN_ROTARY: TIDA-01067 Smart Damper_Sheet1 (Q2.1), TIDA-01067 Smart Damper_Sheet2 (R12.1 U9.10)
I2C_SCL: TIDA-01067 Smart Damper_Sheet1 (U2.6 U4.A1 U5.4), TIDA-01067 Smart Damper_Sheet2 (R10.1 TP6.1 U9.7)
I2C_SDA: TIDA-01067 Smart Damper_Sheet1 (U2.1 U4.A2 U5.3), TIDA-01067 Smart Damper_Sheet2 (R9.1 TP5.1 U9.6)
IN1: TIDA-01067 Smart Damper_Sheet1 (U3.9 U3.16), TIDA-01067 Smart Damper_Sheet2 (TP7.1 U9.21)
IN2: TIDA-01067 Smart Damper_Sheet1 (U3.10 U3.15), TIDA-01067 Smart Damper_Sheet2 (TP8.1 U9.22)
nDRDY_HDC: TIDA-01067 Smart Damper_Sheet1 (U4.D2), TIDA-01067 Smart Damper_Sheet2 (R11.1 U9.9)
nFAULT: TIDA-01067 Smart Damper_Sheet1 (R5.1 U3.8), TIDA-01067 Smart Damper_Sheet2 (U9.20)
nSLEEP: TIDA-01067 Smart Damper_Sheet1 (U3.1), TIDA-01067 Smart Damper_Sheet2 (U9.16)

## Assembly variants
001: not fitted C4 C11 C19 C23 C24 C28 FID1 FID2 FID3 J4 R12 R12 U2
